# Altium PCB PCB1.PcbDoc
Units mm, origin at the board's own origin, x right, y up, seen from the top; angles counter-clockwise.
Board outline 47.62 x 51.43 mm, 2 copper layers (Top Layer, Bottom Layer); 94 components, 64 nets, 274 pads, 82 vias.
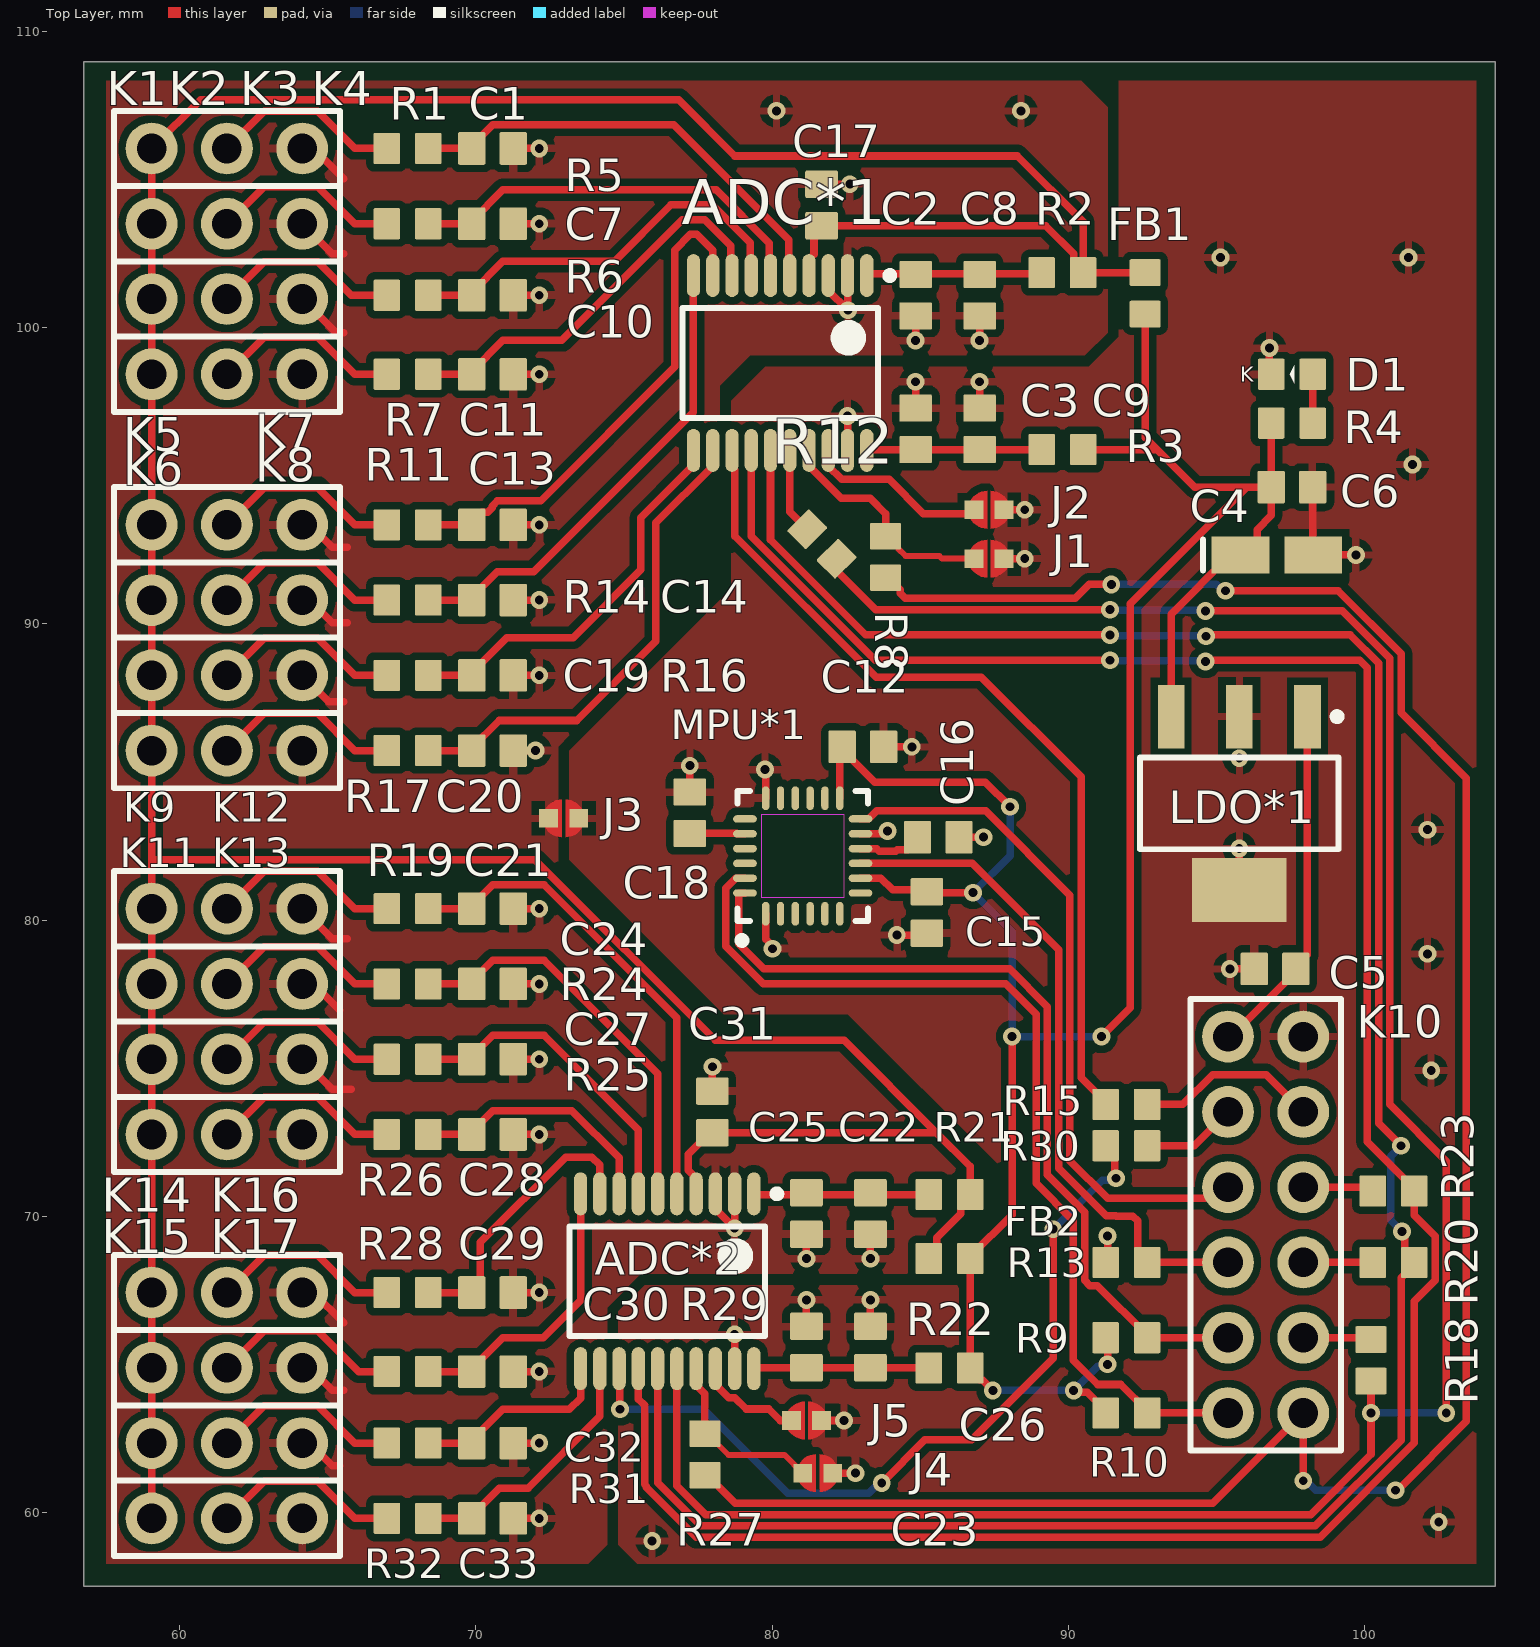
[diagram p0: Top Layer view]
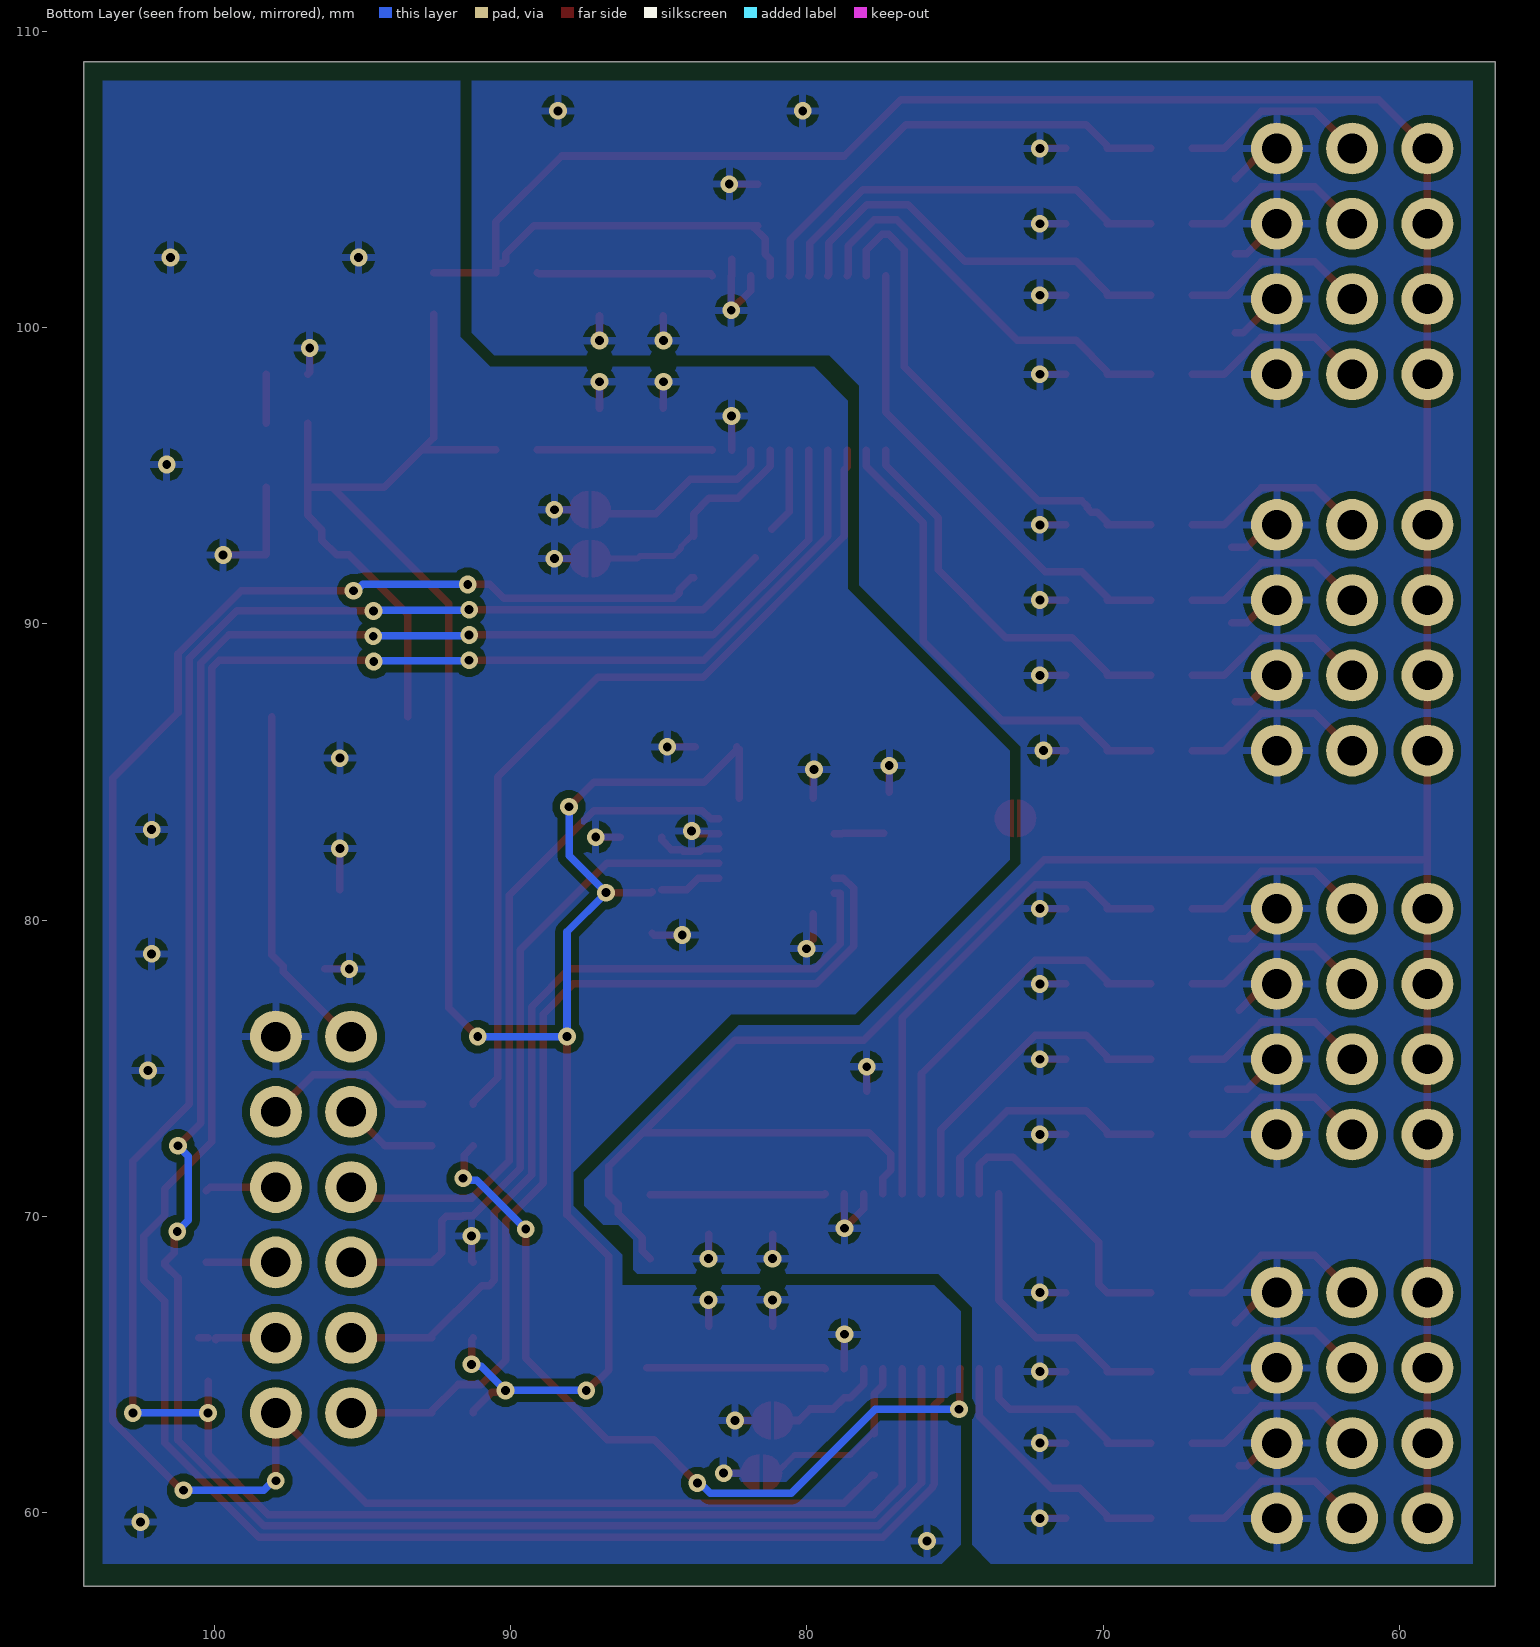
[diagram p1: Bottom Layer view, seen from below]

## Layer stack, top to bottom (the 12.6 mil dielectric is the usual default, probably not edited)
Top Solder: solder mask 0.0102, Solder Resist, Dk 3.5
Top Layer: signal copper 0.0356
Dielectric 1: dielectric 0.32, FR-4, Dk 4.8
Bottom Layer: signal copper 0.0356
Bottom Solder: solder mask 0.0102, Solder Resist, Dk 3.5

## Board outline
56.769,57.531 56.769,108.966 104.394,108.966 104.394,57.531

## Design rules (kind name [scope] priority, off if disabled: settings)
Clearance [All] p1: gap=0.254 ignorepadtopadclearanceinfootprint=TRUE except(0: Arc-Hole Track-Hole SMDPad-Hole THPad-Hole Via-Hole Fill-Hole Poly-Hole Region-Hole Text-Hole; 0.127: Arc-Arc Arc-Track Arc-SMDPad Track-Track Track-SMDPad SMDPad-SMDPad SMDPad-Fill Region-Region)
PolygonConnect [All] p1: connectstyle=Relief reliefconductorwidth=0.254 reliefentries=4 polygonreliefangle="90 Angle" airgapwidth=0.254
RoutingVias [All] p1: holewidth=0.3 width=0.6 viastyle="Through Hole" minholewidth=0.1 minwidth=0.1 maxholewidth=0.711 maxwidth=1.27
SilkToSilkClearance [All] p1: silktosilkclearance=0.1
SolderMaskExpansion [All] p1: expansion=0.102 istentingtop=FALSE
Width [All] p1: maxlimit=0.254 minlimit=0.127 preferedwidth=0.254 bottomlayer_minwidth=0.254 minimp=50.000000 maximp=50.000000 favimp=50.000000
29 further rules are at their usual default settings.

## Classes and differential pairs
component class Sheet1: ADC1 ADC2 C1 C2 C3 C4 C5 C6 C7 C8 C9 C10 C11 C12 C13 C14 C15 C16 C17 C18 C19 C20 C21 C22 C23 C24 C25 C26 C27 C28 C29 C30 C31 C32 C33 D1 FB1 FB2 K1 K2 K3 K4 K5 K6 K7 K8 K9 K10 K11 K12 K13 K14 K15 K16 K17 LDO1 MPU1 R1 R2 R3 R4 R5 R6 R7 R8 R9 R10 R11 R12 R13 R14 R15 R16 R17 R18 R19 R20 R21 R22 R23 R24 R25 R26 R27 R28 R29 R30 R31 R32

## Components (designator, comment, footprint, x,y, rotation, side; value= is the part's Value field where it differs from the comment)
ADC*1 "MCP3464" "TSOP65P640X120-20N ADC" 80.264,98.806 r270 top
ADC*2 "MCP3464" "TSOP65P640X120-20N ADC" 76.454,67.818 r270 top
C1 "0.1uF" C1608_0603I_M 70.557,106.045 r180 top
C2 "0.1uF" C1608_0603I_M 84.836,101.092 r270 top
C3 "0.1uF" C1608_0603I_M 84.836,96.585 r270 top
C4 "10uF" "C Tantal A" 97.028,92.329 r0 top
C5 "4.7uF" C1608_0603I_M 96.963,78.359 r180 top
C6 "4.7uF" C1608_0603I_M 97.536,94.615 r0 top
C7 "0.1uF" C1608_0603I_M 70.557,103.505 r180 top
C8 "0.1uF" C1608_0603I_M 86.995,101.092 r270 top
C9 "0.1uF" C1608_0603I_M 86.995,96.585 r270 top
C10 "0.1uF" C1608_0603I_M 70.557,101.092 r180 top
C11 "0.1uF" C1608_0603I_M 70.557,98.425 r180 top
C12 "0.1uF" C1608_0603I_M 83.058,85.852 r180 top
C13 "0.1uF" C1608_0603I_M 70.557,93.345 r180 top
C14 "0.1uF" C1608_0603I_M 70.557,90.805 r180 top
C15 "10nF" C1608_0603I_M 85.217,80.264 r270 top
C16 "0.1uF" C1608_0603I_M 85.598,82.804 r180 top
C17 "0.1uF" C1608_0603I_M 81.661,104.14 r270 top
C18 "2.2nF" C1608_0603I_M 77.216,83.628 r90 top
C19 "0.1uF" C1608_0603I_M 70.557,88.265 r180 top
C20 "0.1uF" C1608_0603I_M 70.557,85.725 r180 top
C21 "0.1uF" C1608_0603I_M 70.557,80.391 r180 top
C22 "0.1uF" C1608_0603I_M 83.312,70.104 r270 top
C23 "0.1uF" C1608_0603I_M 81.153,65.597 r270 top
C24 "0.1uF" C1608_0603I_M 70.557,77.851 r180 top
C25 "0.1uF" C1608_0603I_M 81.153,70.104 r270 top
C26 "0.1uF" C1608_0603I_M 83.312,65.597 r270 top
C27 "0.1uF" C1608_0603I_M 70.557,75.311 r180 top
C28 "0.1uF" C1608_0603I_M 70.557,72.771 r180 top
C29 "0.1uF" C1608_0603I_M 70.557,67.437 r180 top
C30 "0.1uF" C1608_0603I_M 70.557,64.77 r180 top
C31 "0.1uF" C1608_0603I_M 77.978,73.533 r270 top
C32 "0.1uF" C1608_0603I_M 70.557,62.357 r180 top
C33 "0.1uF" C1608_0603I_M 70.557,59.817 r180 top
D1 "LED" LED1608_0603I_M 97.536,98.425 r0 top
FB1 "FERITTE BEAD" R1608_0603I_M 92.583,101.157 r90 top
FB2 "FERITTE BEAD" R1608_0603I_M 85.979,68.58 r180 top
J1 "JMP_mini" solderJumper 87.312,92.202 r180 top
J2 "JMP_mini" solderJumper 87.312,93.853 r180 top
J3 "JMP_mini" solderJumper 72.958,83.44 r0 top
J4 "JMP_mini" solderJumper 81.534,61.341 r180 top
J5 "JMP_mini" solderJumper 81.155,63.119 r180 top
K1 "H1x3" H1x3 59.055,106.045 r180 top
K2 "H1x3" H1x3 59.055,103.505 r180 top
K3 "H1x3" H1x3 59.055,100.965 r180 top
K4 "H1x3" H1x3 59.055,98.425 r180 top
K5 "H1x3" H1x3 59.055,93.345 r180 top
K6 "H1x3" H1x3 59.055,90.805 r180 top
K7 "H1x3" H1x3 59.055,88.265 r180 top
K8 "H1x3" H1x3 59.055,85.725 r180 top
K9 "H1x3" H1x3 59.055,80.391 r180 top
K10 "H2x6" H2x6 97.917,63.373 r270 top
K11 "H1x3" H1x3 59.055,77.851 r180 top
K12 "H1x3" H1x3 59.055,75.311 r180 top
K13 "H1x3" H1x3 59.055,72.771 r180 top
K14 "H1x3" H1x3 59.055,67.437 r180 top
K15 "H1x3" H1x3 59.055,64.897 r180 top
K16 "H1x3" H1x3 59.055,62.357 r180 top
K17 "H1x3" H1x3 59.055,59.817 r180 top
LDO*1 "TC1108" "SOT230P700X180-4N 3V3 LDO" 95.758,83.947 r270 top
MPU*1 "MPU6050" QFN50P400X400X95_HS-25N 81.026,82.169 r90 top
R1 "1k" R1608_0603I_M 67.691,106.045 r0 top
R2 "10" R1608_0603I_M 89.789,101.854 r180 top
R3 "10" R1608_0603I_M 89.789,95.885 r180 top
R4 "1k" R1608_0603I_M 97.536,96.774 r0 top
R5 "1k" R1608_0603I_M 67.691,103.505 r0 top
R6 "1k" R1608_0603I_M 67.691,101.092 r0 top
R7 "1k" R1608_0603I_M 67.691,98.425 r0 top
R8 "10" R1608_0603I_M 83.82,92.264 r270 top
R9 "4k7" R1608_0603I_M 91.948,65.913 r180 top
R10 "4k7" R1608_0603I_M 91.948,63.373 r0 top
R11 "1k" R1608_0603I_M 67.691,93.345 r0 top
R12 "10" R1608_0603I_M 81.674,92.697 r315 top
R13 "4k7" R1608_0603I_M 91.948,68.453 r180 top
R14 "1k" R1608_0603I_M 67.691,90.805 r0 top
R15 "10" R1608_0603I_M 91.948,73.787 r0 top
R16 "1k" R1608_0603I_M 67.691,88.265 r0 top
R17 "1k" R1608_0603I_M 67.691,85.725 r0 top
R18 "10" R1608_0603I_M 100.203,65.151 r90 top
R19 "1k" R1608_0603I_M 67.691,80.391 r0 top
R20 "10" R1608_0603I_M 100.965,68.453 r180 top
R21 "10" R1608_0603I_M 85.979,70.739 r180 top
R22 "10" R1608_0603I_M 85.979,64.897 r180 top
R23 "10" R1608_0603I_M 100.965,70.866 r180 top
R24 "1k" R1608_0603I_M 67.691,77.851 r0 top
R25 "1k" R1608_0603I_M 67.691,75.311 r0 top
R26 "1k" R1608_0603I_M 67.691,72.771 r0 top
R27 "10" R1608_0603I_M 77.724,61.976 r270 top
R28 "1k" R1608_0603I_M 67.691,67.437 r0 top
R29 "1k" R1608_0603I_M 67.691,64.77 r0 top
R30 "10" R1608_0603I_M 91.948,72.39 r0 top
R31 "1k" R1608_0603I_M 67.691,62.357 r0 top
R32 "1k" R1608_0603I_M 67.691,59.817 r0 top

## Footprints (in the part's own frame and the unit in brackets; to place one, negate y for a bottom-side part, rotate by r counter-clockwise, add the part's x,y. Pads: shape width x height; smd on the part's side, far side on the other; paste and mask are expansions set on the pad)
C1608_0603I_M [mm] "Chip Capacitor, 2-Leads, Body 1.57x0.85mm, IPC Low Density"
  rrect10% 0.92x1.1 smd: 1(-0.7,0) 2(0.7,0)
  body extent -0.82,-0.48 0.82,0.48, height 0.95
"C Tantal A" [mm] "Molded Capacitor, 2-Leads, Body 3,2x1,6mm, IPC Medium Density"
  rect 1.95x1.25 smd: 1(-1.225,0) 2(1.225,0)
  silkscreen extent -2.5,-0.53 -2.5,0.53, body extent -1.6,-0.81 1.6,0.79, height 1.63
H1x3 [mm]
  round 1.75 hole 1: 1(0,0) 2(-2.54,0) 3(-5.08,0)
  silkscreen extent -6.35,-1.27 1.27,1.27, body extent -6.35,-1.27 1.27,1.27, height 8.4
H2x6 [mm]
  round 1.75 hole 1: 1(0,0) 2(0,-2.54) 3(-2.54,0) 4(-2.54,-2.54) 5(-5.08,0) 6(-5.08,-2.54) 7(-7.62,0) 8(-7.62,-2.54) 9(-10.16,0) 10(-10.16,-2.54) 11(-12.7,0) 12(-12.7,-2.54)
  silkscreen extent -13.97,-3.81 1.27,1.27, body extent -13.97,-3.81 1.27,1.27, height 8.4
LED1608_0603I_M [mm] "SMD LED, 2-Leads, Body 1.57x0.85mm, IPC Low Density"
  rrect10% 0.9x1.05 smd: 1(-0.7,0) 2(0.7,0)
  silkscreen extent -0.07,-0.3 0.08,0.3, body extent -0.8,-0.4 0.8,0.4, height 0.7
QFN50P400X400X95_HS-25N [mm] "QFN, 24-Leads, Body 4.00x4.00mm, Pitch 0.50mm, Thermal Pad 2.60x2.70mm, IPC Medium Density"
  oval 0.8x0.25 smd: 1(-1.95,1.25) 2(-1.95,0.75) 3(-1.95,0.25) 4(-1.95,-0.25) 5(-1.95,-0.75) 6(-1.95,-1.25) 13(1.95,-1.25) 14(1.95,-0.75) 15(1.95,-0.25) 16(1.95,0.25) 17(1.95,0.75) 18(1.95,1.25)
  oval 0.25x0.8 smd: 7(-1.25,-1.95) 8(-0.75,-1.95) 9(-0.25,-1.95) 10(0.25,-1.95) 11(0.75,-1.95) 12(1.25,-1.95) 19(1.25,1.95) 20(0.75,1.95) 21(0.25,1.95) 22(-0.25,1.95) 23(-0.75,1.95) 24(-1.25,1.95)
  silkscreen extent -2.97,-2.2 2.2,2.2, body extent -2.05,-2.05 2.05,2.05, height 0.95
R1608_0603I_M [mm] "Chip Resistor, 2-Leads, Body 1.57x0.85mm, IPC Low Density"
  rrect10% 0.9x1.05 smd: 1(-0.7,0) 2(0.7,0)
  body extent -0.83,-0.48 0.82,0.48, height 0.5
solderJumper [mil]
  rect 25x25 smd: 1(20,0) 2(-20,0)
  Top Layer region: -2.51,25 -12.08,23.1 -20.19,17.68 -25.61,9.57 -27.51,0 -27.51,0 -25.61,-9.57 -20.19,-17.68 -12.08,-23.1 -2.51,-25 -2.51,-25
  Top Layer region: 2.51,25 12.08,23.1 20.19,17.68 25.61,9.57 27.51,0 27.51,0 25.61,-9.57 20.19,-17.68 12.08,-23.1 2.51,-25 2.51,-25
"SOT230P700X180-4N 3V3 LDO" [mm] "SOT223, 4-Leads, Body 6.50x7.00mm (avg), Pitch 2.30mm, IPC Medium Density"
  rect 2.15x0.9 smd: 1(-2.925,2.3) 2(-2.925,0) 3(-2.925,-2.3)
  rect 2.15x3.2 smd: 2(2.925,0)
  silkscreen extent -3.05,-3.35 1.55,3.43, body extent -3.5,-3.35 3.5,3.35, height 1.8
"TSOP65P640X120-20N ADC" [mm] "TSOP, 20-Leads, Body 6.50x4.40mm, Pitch 0.65mm, IPC Medium Density"
  oval 1.45x0.45 smd: 1(-2.95,2.925) 2(-2.95,2.275) 3(-2.95,1.625) 4(-2.95,0.975) 5(-2.95,0.325) 6(-2.95,-0.325) 7(-2.95,-0.975) 8(-2.95,-1.625) 9(-2.95,-2.275) 10(-2.95,-2.925) 11(2.95,-2.925) 12(2.95,-2.275) 13(2.95,-1.625) 14(2.95,-0.975) 15(2.95,-0.325) 16(2.95,0.325) 17(2.95,0.975) 18(2.95,1.625) 19(2.95,2.275) 20(2.95,2.925)
  silkscreen extent -3.07,-3.3 1.85,3.83, body extent -3.2,-3.3 3.2,3.3, height 1.2

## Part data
C1 C2 C3 C5 C6 C7 C8 C9 C10 C11 C12 C13 C14 C15 C16 C17 C18 C19 C20 C21 C22 C23 C24 C25 C26 C27 C28 C29 C30 C31 C32 C33: library part C, "Capacitor"
C4: library part C+, "Capacitor Polarized"
K1 K2 K3 K4 K5 K6 K7 K8 K9 K11 K12 K13 K14 K15 K16 K17: "Header 1x3 (male)"
K10: "Header 2x5 (male)"
R1 R2 R3 R4 R5 R6 R7 R8 R9 R10 R11 R12 R13 R14 R15 R16 R17 R18 R19 R20 R21 R22 R23 R24 R25 R26 R27 R28 R29 R30 R31 R32: library part R, "R"

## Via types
v1: diameter 0.6, hole 0.3, Top Layer to Bottom Layer, 82 vias

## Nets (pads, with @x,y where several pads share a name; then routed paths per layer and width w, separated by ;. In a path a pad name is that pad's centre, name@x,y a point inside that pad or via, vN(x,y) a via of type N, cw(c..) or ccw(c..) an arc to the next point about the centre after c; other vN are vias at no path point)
+5V: C5.1 K10.12 LDO*1.1 | length 12
  Top Layer w0.254: K10.12 95.467,76.073 97.663,78.269 C5.1 97.663,78.449 98.058,78.844 LDO*1.1
AD0: K10.6 MPU*1.9 R13.1 | length 22.9
  Top Layer w0.254: MPU*1.9 86.747,81.919 89.662,79.004 89.662,71.628 91.267,70.023 91.595,70.023 91.599,70.019 92.16,70.019 92.325,69.854 92.325,68.776 R13.1 K10.6
AVCC: ADC*1.4 ADC*2.4 C17.2 C31.2 FB1.2 FB2.2 K1.1 K2.1 K3.1 K4.1 K5.1 K6.1 K7.1 K8.1 K9.1 K11.1 K12.1 K13.1 K14.1 K15.1 K16.1 K17.1 R2.1 R21.1 | length 140.9
  Top Layer w0.254: K17.1 K16.1 K15.1 K14.1 K13.1 K12.1 K11.1 K9.1 59.055,82.042 ; ADC*2.4 77.429,71.295 77.16,71.564 77.16,72.105 77.888,72.833 C31.2 85.536,72.833 ; ADC*1.4 81.239,102.309 81.407,102.477 81.407,102.997 C17.2@81.788,103.378 ; C17.2 81.788,103.44 89.219,103.44 90.166,102.493 90.166,102.252 90.248,102.17 R2.1@90.489,102.17 ; FB2.2 85.547,68.848 85.547,69.291 86.356,70.1 86.356,70.416 R21.1 86.679,71.69 85.536,72.833 ; FB1.2 90.492,101.857 R2.1 R2.1@90.489,102.17 ; 59.055,82.042 K8.1 K7.1 K6.1 K5.1 K4.1 K3.1 K2.1 K1.1 60.706,107.696 76.835,107.696 78.74,105.791 88.265,105.791 90.489,103.567 R2.1@90.489,102.17 ; 59.055,82.042 71.987,82.042 78.083,75.946 82.423,75.946 85.536,72.833
CS1: K10.9 R15.2 | length 5.9
  Top Layer w0.254: R15.2@92.964,73.787 93.855,73.787 94.857,74.789 96.661,74.789 K10.9
CS2: K10.10 R30.2 | length 3.2
  Top Layer w0.254: R30.2 94.234,72.39 K10.10
DVCC: C4.1 C6.1 C12.2 C15.1 FB1.1 FB2.1 LDO*1.3 MPU*1.8 MPU*1.13 R3.1 R4.1 R9.2 R10.1 R22.1 | length 86.9
  Top Layer w0.254: MPU*1.13 C12.2@82.276,85.77 ; C12.2 82.358,85.762 83.457,84.663 87.189,84.663 v1(88.022,83.831) ; MPU*1.8 82.978,81.417 83.666,81.417 84.057,81.026 C15.1@84.898,81.026 ; C15.1 85.25,80.931 v1(86.773,80.931) ; v1(87.441,64.135) 87.077,64.499 87.002,64.499 86.679,64.822 R22.1 FB2.1 86.679,68.655 88.092,70.068 v1(88.092,76.073) ; v1(90.17,64.135) 90.236,64.069 90.627,64.069 91.248,63.448 R10.1 ; R3.1 92.989,95.885 ; v1(91.105,76.073) 92.075,77.043 92.075,90.678 96.012,94.615 ; R9.2 91.313,65.848 v1(91.313,65.015) ; FB1.1 92.583,96.291 92.989,95.885 ; LDO*1.3 93.458,90.334 95.453,92.329 95.863,92.329 96.361,92.827 96.361,93.186 96.836,93.661 C6.1 ; R4.1 C6.1 ; 92.989,95.885 94.259,94.615 96.012,94.615 ; 96.012,94.615 C6.1
  Bottom Layer w0.254: v1(87.441,64.135) v1(90.17,64.135) 90.984,64.949 91.247,64.949 v1(91.313,65.015) ; v1(88.022,83.831) 88.022,82.18 v1(86.773,80.931) 88.092,79.611 v1(88.092,76.073) v1(91.105,76.073)
GNDA: ADC*1.2 ADC*1.3 ADC*2.2 ADC*2.3 C1.1 C2.2 C7.1 C8.2 C10.1 C11.1 C13.1 C14.1 C17.1 C19.1 C20.1 C21.1 C22.2 C24.1 C25.2 C27.1 C28.1 C29.1 C30.1 C31.1 C32.1 C33.1 J3.2 K1.3 K2.3 K3.3 K4.3 K5.3 K6.3 K7.3 K8.3 K9.3 K11.3 K12.3 K13.3 K14.3 K15.3 K16.3 K17.3 | length 46.5
  Top Layer w0.254: K16.3 64.387,62.357 65.149,61.595 65.405,61.595 ; K15.3 64.387,64.897 65.149,64.135 65.532,64.135 ; K14.3 64.516,67.437 65.532,66.421 ; K12.3 65.151,74.295 65.786,74.295 ; K11.3 64.516,77.851 65.405,76.962 ; K9.3 65.151,79.375 65.659,79.375 ; K7.3 65.024,87.376 65.532,87.376 ; K6.3 64.387,90.805 65.149,90.043 65.659,90.043 ; K5.3 64.387,93.345 65.149,92.583 65.659,92.583 ; K3.3 65.278,99.822 65.532,99.822 ; K2.3 65.151,102.489 65.532,102.489 ; K1.3 64.516,106.045 65.532,105.029 ; C33.1 v1(72.136,59.817) ; C32.1 v1(72.136,62.357) ; C30.1 v1(72.136,64.77) ; C29.1 v1(72.136,67.437) ; C28.1 v1(72.136,72.771) ; C27.1 v1(72.136,75.311) ; C24.1 v1(72.136,77.851) ; C21.1 v1(72.136,80.391) ; C20.1 v1(72.009,85.725) ; C19.1 v1(72.136,88.265) ; C14.1 v1(72.136,90.805) ; C13.1 v1(72.136,93.345) ; C11.1 v1(72.136,98.425) ; C10.1 v1(72.136,101.092) ; C7.1 v1(72.136,103.505) ; C1.1 v1(72.136,106.045) ; C31.1 v1(77.978,75.057) ; ADC*2.3 78.079,70.257 v1(78.729,69.607) ADC*2.2 ; v1(81.153,68.58) C25.2 ; C17.1 v1(82.615,104.84) ; ADC*1.3 81.889,101.25 v1@82.545,100.595 ; ADC*1.2@82.539,102.309 ADC*1.2 82.545,101.75 v1@82.545,100.595 ; v1(82.55,100.584) 82.55,100.589 v1@82.545,100.595 ; v1(83.312,68.58) C22.2 ; v1(84.836,99.568) C2.2 ; v1(86.995,99.568) C8.2
  other v1: 80.137,107.315 88.392,107.315
GNDD: ADC*1.19 ADC*2.19 C3.1 C4.2 C5.2 C6.2 C9.1 C12.1 C15.2 C16.1 C18.2 C23.1 C26.1 D1.1 J1.2 J2.2 J3.1 J4.2 J5.2 K10.11 LDO*1.2 MPU*1.1 MPU*1.11 MPU*1.18 R13.2 | length 23.6
  Top Layer w0.254: C18.2 v1(77.216,85.217) ; ADC*2.19 v1(78.729,66.029) ; v1(79.756,85.09) 79.774,85.072 79.774,84.121 MPU*1.18 ; MPU*1.1 79.776,79.368 80.01,79.134 v1(80.01,79.04) ; C23.1 v1(81.153,67.183) ; J5.2@81.534,63.119 v1(82.423,63.119) ; J4.2 v1(82.804,61.341) ; ADC*1.19 v1(82.539,97.017) ; MPU*1.11 82.978,82.921 83.699,82.921 83.79,83.012 v1(83.884,83.012) ; C26.1 v1(83.312,67.183) ; C12.1 v1(84.709,85.852) ; v1(84.201,79.502) 85.155,79.502 C15.2 ; C3.1 v1(84.836,98.171) ; C16.1 v1(87.122,82.804) ; C9.1 v1(86.995,98.171) ; J1.2 v1(88.519,92.202) ; J2.2 v1(88.519,93.853) ; R13.2 91.313,68.518 v1(91.313,69.342) ; v1(95.439,78.359) C5.2 ; LDO*1.2@95.758,81.022 v1(95.758,82.423) ; v1(96.774,99.314) 96.774,98.487 D1.1 ; C6.2 98.236,92.346 C4.2 v1(99.695,92.329)
  other v1: 75.946,59.055 102.489,59.69 102.235,74.93 102.108,78.867 102.108,83.058 95.758,85.471 101.6,95.377 95.123,102.362 101.473,102.362
INT: K10.8 MPU*1.12 | length 23.3
  Top Layer w0.254: MPU*1.12 83.247,83.419 83.521,83.693 87.196,83.693 90.043,80.846 90.043,71.882 91.313,70.612 94.591,70.612 94.972,70.993 K10.8
MDAT: K10.1 R8.2 R27.2 | length 76.5
  Top Layer w0.254: R27.2 77.799,61.276 78.75,60.325 94.869,60.325 K10.1 v1(97.917,61.087) ; R8.2 83.895,91.564 84.311,91.148 84.311,91.038 84.486,90.863 90.228,90.863 90.699,91.334 v1(91.441,91.334) ; v1(95.294,91.122) 99.09,91.122 101.219,88.992 101.219,86.995 103.424,84.79 103.424,63.091 101.098,60.765 v1(101.033,60.765)
  Bottom Layer w0.254: v1(91.441,91.334) 94.988,91.334 95.2,91.122 v1(95.294,91.122) ; v1(97.917,61.087) 98.011,61.087 98.332,60.765 v1(101.033,60.765)
MISO: ADC*2.16 R12.2 R18.1 | length 80.4
  Top Layer w0.254: ADC*2.16 76.779,60.913 77.748,59.944 98.171,59.944 100.203,61.976 v1(100.203,63.373) R18.1 ; R12.2@81.743,92.234 83.496,90.481 v1(91.394,90.481) ; v1(94.62,90.441) 99.232,90.441 100.838,88.835 100.838,73.787 102.75,71.875 102.75,64.396 102.743,64.389 v1(102.743,63.373)
  Bottom Layer w0.254: v1(91.394,90.481) 91.414,90.461 94.6,90.461 v1(94.62,90.441) ; v1(100.203,63.373) v1(102.743,63.373)
MOSI: ADC*1.15 ADC*2.15 R20.1 | length 83.2
  Top Layer w0.254: ADC*2.15 76.129,61.024 77.59,59.563 98.329,59.563 101.219,62.453 101.219,67.932 101.665,68.378 R20.1 101.342,68.776 101.342,69.305 101.245,69.402 v1(101.245,69.495) ; ADC*1.15 79.939,92.846 83.158,89.627 v1(91.394,89.627) ; v1(94.631,89.583) 94.675,89.627 99.507,89.627 100.457,88.677 100.457,73.152 v1(101.219,72.39)
  Bottom Layer w0.254: v1(91.394,89.627) 91.416,89.605 94.609,89.605 v1(94.631,89.583) ; v1(101.219,72.39) 100.871,72.042 100.871,69.87 v1(101.245,69.495)
NetADC*1_1: ADC*1.1 C2.1 C8.1 R2.2 | length 5.9
  Top Layer w0.254: ADC*1.1 83.248,101.815 89.05,101.815 R2.2
NetADC*1_5: ADC*1.5 C1.2 R1.2 | length 15.4
  Top Layer w0.254: R1.2 C1.2 69.857,106.135 70.571,106.849 76.666,106.849 80.551,102.964 80.551,101.794 ADC*1.5
NetADC*1_6: ADC*1.6 C7.2 R5.2 | length 13.9
  Top Layer w0.254: R5.2 C7.2 69.857,103.595 70.91,104.648 78.105,104.648 79.901,102.852 79.901,101.794 ADC*1.6
NetADC*1_7: ADC*1.7 C10.2 R6.2 | length 13.8
  Top Layer w0.254: R6.2 C10.2 69.857,101.182 70.91,102.235 74.676,102.235 76.581,104.14 77.978,104.14 79.251,102.867 79.251,101.794 ADC*1.7
NetADC*1_8: ADC*1.8 C11.2 R7.2 | length 13.8
  Top Layer w0.254: R7.2 C11.2 69.857,98.515 70.91,99.568 72.898,99.568 76.962,103.632 77.724,103.632 78.601,102.755 78.601,101.794 ADC*1.8
NetADC*1_9: ADC*1.9 C13.2 R11.2 | length 17.1
  Top Layer w0.254: R11.2 C13.2 69.857,93.435 70.19,93.768 70.394,93.768 70.543,93.917 70.543,93.973 70.719,94.149 72.178,94.149 76.708,98.679 76.708,102.616 77.238,103.146 77.448,103.146 77.989,102.605 ADC*1.9
NetADC*1_10: ADC*1.10 C14.2 R14.2 | length 16.2
  Top Layer w0.254: R14.2 C14.2 69.857,90.895 70.719,91.757 71.945,91.757 77.339,97.151 ADC*1.10
NetADC*1_11: ADC*1.11 C19.2 R16.2 | length 13.5
  Top Layer w0.254: R16.2 C19.2 69.857,88.355 71.037,89.535 73.279,89.535 75.565,91.821 75.565,93.582 77.339,95.356 ADC*1.11
NetADC*1_12: ADC*1.12 C20.2 R17.2 | length 16.5
  Top Layer w0.254: R17.2 C20.2 69.857,85.815 70.783,86.741 73.406,86.741 76.073,89.408 76.073,93.413 77.989,95.329 ADC*1.12
NetADC*1_13: ADC*1.13 R15.1 | length 29.4
  Top Layer w0.254: ADC*1.13 78.639,95.303 78.74,95.202 78.74,92.967 83.5,88.207 87.053,88.207 90.424,84.836 90.424,74.686 91.248,73.862 R15.1
NetADC*1_16: ADC*1.16 R12.1 | length 2.9
  Top Layer w0.254: ADC*1.16 80.589,93.782 R12.1
NetADC*1_17: ADC*1.17 J1.1 R8.1 | length 7.9
  Top Layer w0.2: R8.1 83.895,92.964 84.245,92.614 84.245,92.542 84.497,92.29 85.637,92.29 85.725,92.202 J1.1 J1.1@86.762,92.244
  Top Layer w0.254: ADC*1.17 81.239,95.329 82.334,94.234 83.312,94.234 83.82,93.726 R8.1
NetADC*1_18: ADC*1.18 J2.1 | length 6.2
  Top Layer w0.254: ADC*1.18 81.889,95.329 82.341,94.877 83.939,94.877 85.09,93.726 86.677,93.726 J2.1
NetADC*1_20: ADC*1.20 C3.2 C9.2 R3.2 | length 5.9
  Top Layer w0.254: ADC*1.20 83.213,95.88 89.084,95.88 R3.2
NetADC*2_1: ADC*2.1 C22.1 C25.1 R21.2 | length 5.9
  Top Layer w0.254: ADC*2.1 79.403,70.744 85.274,70.744 R21.2
NetADC*2_5: ADC*2.5 C21.2 R19.2 | length 16.6
  Top Layer w0.254: R19.2 C21.2 69.857,80.481 70.571,81.195 72.295,81.195 76.779,76.711 ADC*2.5
NetADC*2_6: ADC*2.6 C24.2 R24.2 | length 13.8
  Top Layer w0.254: R24.2 C24.2 69.857,77.941 70.571,78.655 72.295,78.655 76.129,74.821 ADC*2.6
NetADC*2_7: ADC*2.7 C27.2 R25.2 | length 11
  Top Layer w0.254: R25.2 C27.2 69.857,75.401 70.571,76.115 72.295,76.115 75.479,72.931 ADC*2.7
NetADC*2_8: ADC*2.8 C28.2 R26.2 | length 8.7
  Top Layer w0.254: R26.2 C28.2 69.857,72.861 70.571,73.575 73.237,73.575 74.829,71.983 ADC*2.8
NetADC*2_9: ADC*2.9 C29.2 R28.2 | length 9.6
  Top Layer w0.254: R28.2 C29.2 70.144,67.724 70.144,69.128 73.025,72.009 73.914,72.009 74.179,71.744 ADC*2.9
NetADC*2_10: ADC*2.10 C30.2 R29.2 | length 9.8
  Top Layer w0.254: R29.2 C30.2 69.857,64.86 70.91,65.913 72.263,65.913 73.529,67.179 ADC*2.10
NetADC*2_11: ADC*2.11 C32.2 R31.2 | length 6.8
  Top Layer w0.254: R31.2 C32.2 69.857,62.447 70.91,63.5 73.152,63.5 73.529,63.877 ADC*2.11
NetADC*2_12: ADC*2.12 C33.2 R32.2 | length 8.9
  Top Layer w0.254: R32.2 C33.2 69.857,59.907 70.783,60.833 71.755,60.833 74.179,63.257 ADC*2.12
NetADC*2_13: ADC*2.13 R30.1 | length 27.5
  Top Layer w0.254: ADC*2.13 74.845,64.852 74.845,63.515 v1(74.86,63.5) ; v1(83.693,61.006) 85.15,62.463 86.732,62.463 89.482,65.213 v1(89.482,69.575) ; R30.1 91.561,72.077 91.561,71.328 v1(91.595,71.293)
  Bottom Layer w0.254: v1(74.86,63.5) 77.684,63.5 80.524,60.66 83.253,60.66 83.599,61.006 v1(83.693,61.006) ; v1(89.482,69.575) 91.134,71.227 91.529,71.227 v1(91.595,71.293)
NetADC*2_17: ADC*2.17 J4.1 R27.1 | length 6.2
  Top Layer w0.2: R27.1 77.799,62.676 78.522,61.953 80.414,61.953 J4.1
  Top Layer w0.254: ADC*2.17 77.429,64.315 77.724,64.02 R27.1
NetADC*2_18: ADC*2.18 J5.1 | length 3.6
  Top Layer w0.254: ADC*2.18 78.079,64.341 78.531,63.889 78.739,63.889 79.121,63.507 79.879,63.507 80.268,63.119 J5.1
NetADC*2_20: ADC*2.20 C23.2 C26.2 R22.2 | length 6
  Top Layer w0.254: ADC*2.20 79.404,64.892 81.153,64.892 83.312,64.892 85.401,64.892 R22.2@85.406,64.897
NetC16_2: C16.2 MPU*1.10 | length 2.2
  Top Layer w0.254: MPU*1.10 82.978,82.417 83.516,82.417 83.602,82.331 84.166,82.331 84.216,82.381 84.565,82.381 84.898,82.714 C16.2
NetC18_1: C18.1 MPU*1.20 | length 1.7
  Top Layer w0.254: C18.1@77.408,82.931 78.793,82.931 78.805,82.919 MPU*1.20
NetD1_2: D1.2 R4.2 | length 1.7
  Top Layer w0.254: R4.2 D1.2
NetK1_2: K1.2 R1.1 | length 6.4
  Top Layer w0.254: K1.2 62.851,107.301 64.655,107.301 65.911,106.045 R1.1
NetK2_2: K2.2 R5.1 | length 6.4
  Top Layer w0.254: K2.2 62.851,104.761 64.655,104.761 65.911,103.505 R5.1
NetK3_2: K3.2 R6.1 | length 6.4
  Top Layer w0.254: K3.2 62.851,102.221 64.655,102.221 65.784,101.092 R6.1
NetK4_2: K4.2 R7.1 | length 6.4
  Top Layer w0.254: K4.2 62.851,99.681 64.655,99.681 65.911,98.425 R7.1
NetK5_2: K5.2 R11.1 | length 6.4
  Top Layer w0.254: K5.2 62.851,94.601 64.655,94.601 65.911,93.345 R11.1
NetK6_2: K6.2 R14.1 | length 6.4
  Top Layer w0.254: K6.2 62.851,92.061 64.655,92.061 65.911,90.805 R14.1
NetK7_2: K7.2 R16.1 | length 6.4
  Top Layer w0.254: K7.2 62.851,89.521 64.655,89.521 65.911,88.265 R16.1
NetK8_2: K8.2 R17.1 | length 6.4
  Top Layer w0.254: K8.2 62.851,86.981 64.655,86.981 65.911,85.725 R17.1
NetK9_2: K9.2 R19.1 | length 6.4
  Top Layer w0.254: K9.2 62.851,81.647 64.655,81.647 65.911,80.391 R19.1
NetK10_3: K10.3 R18.2 | length 2.3
  Top Layer w0.254: K10.3 R18.2@99.949,65.913 ; R18.2@100.203,65.913 R18.2@100.519,65.913
NetK10_5: K10.5 R20.2 | length 2.3
  Top Layer w0.254: K10.5 R20.2
NetK10_7: K10.7 R23.2 | length 2.4
  Top Layer w0.254: K10.7 100.138,70.993 R23.2
NetK11_2: K11.2 R24.1 | length 6.4
  Top Layer w0.254: K11.2 62.851,79.107 64.655,79.107 65.911,77.851 R24.1
NetK12_2: K12.2 R25.1 | length 6.4
  Top Layer w0.254: K12.2 62.851,76.567 64.655,76.567 65.911,75.311 R25.1
NetK13_2: K13.2 R26.1 | length 6.4
  Top Layer w0.254: K13.2 62.851,74.027 64.655,74.027 65.911,72.771 R26.1
NetK14_2: K14.2 R28.1 | length 6.4
  Top Layer w0.254: K14.2 62.851,68.693 64.655,68.693 65.911,67.437 R28.1
NetK15_2: K15.2 R29.1 | length 6.5
  Top Layer w0.254: K15.2 62.851,66.153 64.655,66.153 66.038,64.77 R29.1
NetK16_2: K16.2 R31.1 | length 6.4
  Top Layer w0.254: K16.2 62.851,63.613 64.655,63.613 65.911,62.357 R31.1
NetK17_2: K17.2 R32.1 | length 6.4
  Top Layer w0.254: K17.2 62.851,61.073 64.655,61.073 65.911,59.817 R32.1
SCK: ADC*1.14 ADC*2.14 R23.1 | length 85
  Top Layer w0.254: ADC*2.14 75.479,63.844 75.692,63.631 75.692,60.96 75.748,60.904 75.748,60.867 77.433,59.182 98.487,59.182 101.665,62.36 101.665,67.145 102.369,67.849 102.369,69.335 101.665,70.039 101.665,70.941 100.076,72.53 100.076,88.519 99.822,88.773 94.658,88.773 v1(94.614,88.729) ; ADC*1.14 79.289,92.957 83.473,88.773 v1(91.394,88.773)
  Bottom Layer w0.254: v1(91.394,88.773) 91.416,88.751 94.592,88.751 v1(94.614,88.729)
SCL: K10.2 MPU*1.23 R10.2 | length 32.4
  Top Layer w0.254: MPU*1.23 78.765,81.419 78.422,81.076 78.422,79.116 79.687,77.851 87.884,77.851 88.9,76.835 88.9,71.12 90.163,69.857 90.163,65.158 90.987,64.334 91.762,64.334 92.648,63.448 R10.2 K10.2
SDA: K10.4 MPU*1.24 R9.1 | length 28.7
  Top Layer w0.254: MPU*1.24 78.869,80.919 78.867,80.917 78.867,79.21 79.718,78.359 88.011,78.359 89.281,77.089 89.281,71.405 90.544,70.142 90.544,67.849 90.719,67.674 90.962,67.674 92.648,65.988 R9.1 K10.4
pads on no net: MPU*1.2 MPU*1.3 MPU*1.4 MPU*1.5 MPU*1.6 MPU*1.7 MPU*1.14 MPU*1.15 MPU*1.16 MPU*1.17 MPU*1.19 MPU*1.21 MPU*1.22

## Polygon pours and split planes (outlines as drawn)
GNDD on Bottom Layer "GNDD_L02_P003" (solid, pour order 3): 91.694,108.331 91.694,99.695 90.678,98.679 79.756,98.679 78.613,97.536 78.613,91.186 73.152,85.725 73.152,82.042 78.359,76.835 82.55,76.835 87.884,71.501 87.884,70.358 86.233,68.707 86.233,67.691 75.692,67.691 74.803,66.802 74.803,58.928 75.438,58.293 103.759,58.293 103.759,108.331
GNDA on Bottom Layer "GNDA_L02_P001" (solid, pour order 1): 57.531,58.293 73.787,58.293 74.422,58.928 74.422,66.929 75.565,68.072 85.725,68.072 85.852,68.199 85.852,69.215 86.36,69.723 86.868,69.723 87.503,70.358 87.503,71.247 82.296,76.454 78.232,76.454 72.771,81.915 72.771,85.852 78.232,91.313 78.232,98.044 79.248,99.06 90.551,99.06 91.313,99.822 91.313,108.331 57.531,108.331
GNDD on Top Layer "GNDD_L01_P004" (solid, remove dead copper, pour order 4): 91.694,108.331 91.694,99.695 90.678,98.679 79.756,98.679 78.613,97.536 78.613,91.186 73.152,85.725 73.152,82.042 78.359,76.835 82.55,76.835 87.884,71.501 87.884,70.358 86.233,68.707 86.233,67.691 75.692,67.691 74.803,66.802 74.803,58.928 75.438,58.293 103.759,58.293 103.759,108.331
GNDA on Top Layer "tga" (solid, remove dead copper, pour order 2): 57.531,58.293 73.787,58.293 74.422,58.928 74.422,66.929 75.565,68.072 85.852,68.072 85.979,68.199 85.979,69.342 86.36,69.723 86.868,69.723 87.503,70.358 87.503,71.247 82.296,76.454 78.232,76.454 72.771,81.915 72.771,85.852 78.232,91.313 78.232,98.044 79.248,99.06 90.551,99.06 91.313,99.822 91.313,107.442 90.424,108.331 57.531,108.331

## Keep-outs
Top Layer:
  rectangle: 79.629,80.772 82.423,83.566

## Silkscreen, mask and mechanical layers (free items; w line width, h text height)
Mechanical 1:
  lines w0.254: 56.769,57.531 56.769,108.966 57.023,108.966 104.394,108.966 104.394,57.531 56.769,57.531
